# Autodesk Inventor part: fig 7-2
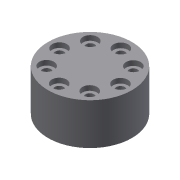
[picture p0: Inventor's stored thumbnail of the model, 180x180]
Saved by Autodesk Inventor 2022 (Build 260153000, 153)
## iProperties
Created: 2004-05
Part Number: fig 7-2
Document SubType Name: Modeling
Designer: CADCIM Technologies
Manufacturer: Standard
Standards Organization: Custom
Density: 1 g/cm^3
Material: Generic
Appearance: Default
Author: CADCIM Technologies
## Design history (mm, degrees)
sketch "Sketch1"
  geometry: C1 r 17.175 at (0, 0)
  constraints: 1 centre point
extrude "Extrusion1" new body sketch "Sketch1" distance "d0" = 17; taper "d1" = 0 deg
sketch "Sketch2"
  geometry: 1 further point
hole "Hole1" sketch "Sketch2" at (12.571, -0.074) diameter "d2" = 3.5; stored, may be unused: countersink angle "d6" = 90 deg, drill point angle "d8" = 118 deg; dims "d3" = 6, "d4" = 6, "d5" = 2, "d7" = 8
pattern_circular "Circular Pattern1" dims angle "d11" = 360 deg
body "Solid1"
